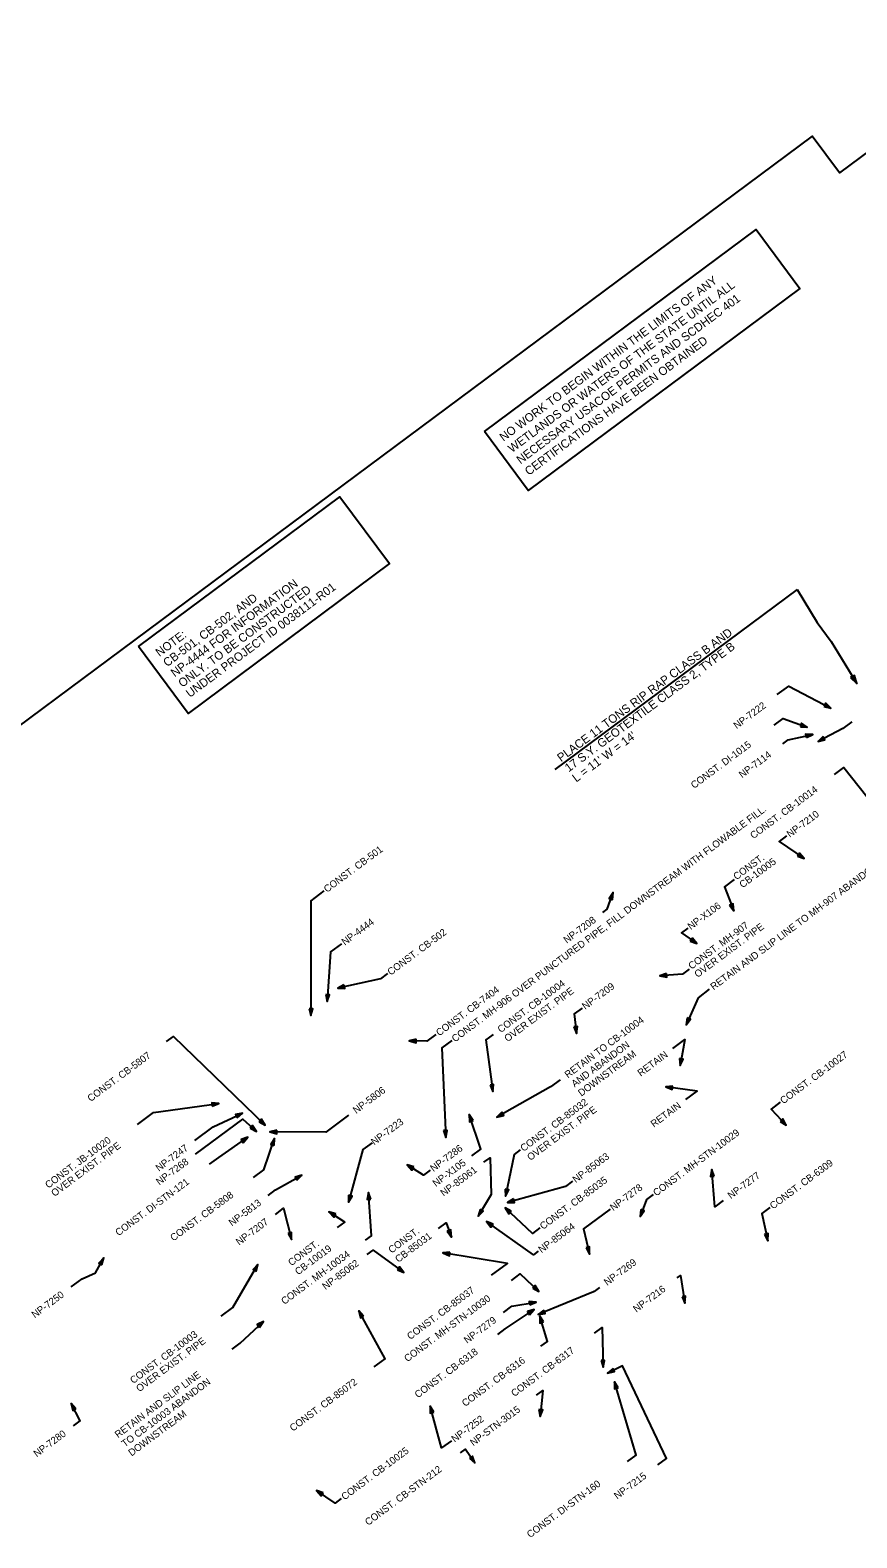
# Model space of a CAD drawing. Extents: x 1612334 to 1614149, y 1094755 to 1096548.
# Drawn here: x 1612860 to 1613444, y 1095452 to 1096518 of the extents above; entities that cross this region are included whole.
import ezdxf

# ---------------------------------------------------------------- set-up
doc = ezdxf.new("R2010")
doc.units = 0
for name, color, linetype in [('Level 11', 7, 'Continuous'), ('Level 15', 7, 'Continuous'), ('RD_HY_DumbNodes', 7, 'Continuous')]:
    doc.layers.add(name, color=color, linetype=linetype)

msp = doc.modelspace()

# ---------------------------------------------------------------- linework, layer by layer
at = {"layer": 'Level 11'}
msp.add_lwpolyline([(1613180.6, 1096234), (1613372.6, 1096376.7), (1613403.5, 1096335.1), (1613211.5, 1096192.4)], close=True, dxfattribs=at)
at = {"layer": 'Level 15'}
msp.add_lwpolyline([(1612485.6, 1095458.4), (1612588.4, 1095320.1), (1612593, 1095313.9), (1612580.2, 1095304.3), (1612634.5, 1095231.1), (1612645.5, 1095216.3), (1612653.4, 1095198.5), (1612742.5, 1095078.7), (1612868, 1094853.9), (1614076.2, 1095752), (1613959.1, 1095956.1), (1613849.9, 1096103.1), (1613853.4, 1096105.7), (1613781.7, 1096202.2), (1613794.6, 1096211.8), (1613636.5, 1096424.5), (1613567.4, 1096517.5), (1613431.6, 1096416.6), (1613412.2, 1096442.7), (1612334.4, 1095641.5)], close=True, dxfattribs=at)
msp.add_lwpolyline([(1612485.6, 1095458.4), (1612588.4, 1095320.1), (1612593, 1095313.9), (1612580.2, 1095304.3), (1612634.5, 1095231.1), (1612645.5, 1095216.3), (1612653.4, 1095198.5), (1612742.5, 1095078.7), (1612868, 1094853.9), (1614076.2, 1095752), (1613959.1, 1095956.1), (1613849.9, 1096103.1), (1613853.4, 1096105.7), (1613781.7, 1096202.2), (1613794.6, 1096211.8), (1613636.5, 1096424.5), (1613567.4, 1096517.5), (1613431.6, 1096416.6), (1613412.2, 1096442.7), (1612334.4, 1095641.5)], close=True, dxfattribs=at)
msp.add_lwpolyline([(1612485.6, 1095458.4), (1612588.4, 1095320.1), (1612593, 1095313.9), (1612580.2, 1095304.3), (1612634.5, 1095231.1), (1612645.5, 1095216.3), (1612653.4, 1095198.5), (1612742.5, 1095078.7), (1612868, 1094853.9), (1614076.2, 1095752), (1613959.1, 1095956.1), (1613849.9, 1096103.1), (1613853.4, 1096105.7), (1613781.7, 1096202.2), (1613794.6, 1096211.8), (1613636.5, 1096424.5), (1613567.4, 1096517.5), (1613431.6, 1096416.6), (1613412.2, 1096442.7), (1612334.4, 1095641.5)], close=True, dxfattribs=at)
msp.add_lwpolyline([(1612485.6, 1095458.4), (1612588.4, 1095320.1), (1612593, 1095313.9), (1612580.2, 1095304.3), (1612634.5, 1095231.1), (1612645.5, 1095216.3), (1612653.4, 1095198.5), (1612742.5, 1095078.7), (1612868, 1094853.9), (1614076.2, 1095752), (1613959.1, 1095956.1), (1613849.9, 1096103.1), (1613853.4, 1096105.7), (1613781.7, 1096202.2), (1613794.6, 1096211.8), (1613636.5, 1096424.5), (1613567.4, 1096517.5), (1613431.6, 1096416.6), (1613412.2, 1096442.7), (1612334.4, 1095641.5)], close=True, dxfattribs=at)
msp.add_lwpolyline([(1612485.6, 1095458.4), (1612588.4, 1095320.1), (1612593, 1095313.9), (1612580.2, 1095304.3), (1612634.5, 1095231.1), (1612645.5, 1095216.3), (1612653.4, 1095198.5), (1612742.5, 1095078.7), (1612868, 1094853.9), (1614076.2, 1095752), (1613959.1, 1095956.1), (1613849.9, 1096103.1), (1613853.4, 1096105.7), (1613781.7, 1096202.2), (1613794.6, 1096211.8), (1613636.5, 1096424.5), (1613567.4, 1096517.5), (1613431.6, 1096416.6), (1613412.2, 1096442.7), (1612334.4, 1095641.5)], close=True, dxfattribs=at)
msp.add_lwpolyline([(1612485.6, 1095458.4), (1612588.4, 1095320.1), (1612593, 1095313.9), (1612580.2, 1095304.3), (1612634.5, 1095231.1), (1612645.5, 1095216.3), (1612653.4, 1095198.5), (1612742.5, 1095078.7), (1612868, 1094853.9), (1614076.2, 1095752), (1613959.1, 1095956.1), (1613849.9, 1096103.1), (1613853.4, 1096105.7), (1613781.7, 1096202.2), (1613794.6, 1096211.8), (1613636.5, 1096424.5), (1613567.4, 1096517.5), (1613431.6, 1096416.6), (1613412.2, 1096442.7), (1612334.4, 1095641.5)], close=True, dxfattribs=at)
msp.add_lwpolyline([(1612485.6, 1095458.4), (1612588.4, 1095320.1), (1612593, 1095313.9), (1612580.2, 1095304.3), (1612634.5, 1095231.1), (1612645.5, 1095216.3), (1612653.4, 1095198.5), (1612742.5, 1095078.7), (1612868, 1094853.9), (1614076.2, 1095752), (1613959.1, 1095956.1), (1613849.9, 1096103.1), (1613853.4, 1096105.7), (1613781.7, 1096202.2), (1613794.6, 1096211.8), (1613636.5, 1096424.5), (1613567.4, 1096517.5), (1613431.6, 1096416.6), (1613412.2, 1096442.7), (1612334.4, 1095641.5)], close=True, dxfattribs=at)
msp.add_lwpolyline([(1612485.6, 1095458.4), (1612588.4, 1095320.1), (1612593, 1095313.9), (1612580.2, 1095304.3), (1612634.5, 1095231.1), (1612645.5, 1095216.3), (1612653.4, 1095198.5), (1612742.5, 1095078.7), (1612868, 1094853.9), (1614076.2, 1095752), (1613959.1, 1095956.1), (1613849.9, 1096103.1), (1613853.4, 1096105.7), (1613781.7, 1096202.2), (1613794.6, 1096211.8), (1613636.5, 1096424.5), (1613567.4, 1096517.5), (1613431.6, 1096416.6), (1613412.2, 1096442.7), (1612334.4, 1095641.5)], close=True, dxfattribs=at)
at = {"layer": 'RD_HY_DumbNodes'}
msp.add_line((1613401.6, 1096122.4), (1613230.5, 1095995.3), dxfattribs=at)
for points in [[(1612936.1, 1096082.1), (1613078.5, 1096187.9), (1613113.6, 1096140.7), (1612971.2, 1096034.8)], [(1613439.4, 1096060.1), (1613443.7, 1096055.9), (1613442.1, 1096061.7)], [(1613420.6, 1096039.7), (1613425.5, 1096038.6), (1613421.8, 1096042)], [(1613403.9, 1096025.4), (1613408.8, 1096025), (1613404.8, 1096027.9)], [(1613408.2, 1096017.7), (1613412.6, 1096020), (1613407.6, 1096020.2)], [(1613420, 1096018.4), (1613416.4, 1096015), (1613421.2, 1096016.1)], [(1613401.9, 1095934), (1613406.6, 1095932.4), (1613403.4, 1095936.2)], [(1613271.2, 1095903.2), (1613271.7, 1095908.2), (1613268.8, 1095904.1)], [(1613353.9, 1095899.4), (1613356.9, 1095895.4), (1613356.3, 1095900.4)], [(1613326.1, 1095874), (1613330.8, 1095872.3), (1613327.6, 1095876.1)], [(1613309.4, 1095851.1), (1613304.7, 1095849.5), (1613309.6, 1095848.6)], [(1613068.5, 1095836.2), (1613069.4, 1095831.3), (1613071.1, 1095836.1)], [(1613081.4, 1095843), (1613077, 1095840.7), (1613082, 1095840.5)], [(1613056.7, 1095826.1), (1613058, 1095821.3), (1613059.3, 1095826.1)], [(1613243.8, 1095813.4), (1613245.6, 1095808.8), (1613246.4, 1095813.7)], [(1613323.9, 1095819.8), (1613323.1, 1095814.9), (1613326.3, 1095818.8)], [(1613132.3, 1095804.7), (1613127.5, 1095803.5), (1613132.3, 1095802.1)], [(1613318.5, 1095791), (1613318.9, 1095786), (1613321.1, 1095790.6)], [(1613184.6, 1095772.3), (1613186.5, 1095767.7), (1613187.1, 1095772.6)], [(1613313.7, 1095771.6), (1613308.8, 1095771), (1613313.4, 1095769.1)], [(1612988.3, 1095757.3), (1612993, 1095759.2), (1612988, 1095759.8)], [(1613005.9, 1095749.2), (1613009.7, 1095752.4), (1613004.8, 1095751.5)], [(1613021.4, 1095746.3), (1613025.8, 1095743.9), (1613023.2, 1095748.2)], [(1613172.6, 1095747.3), (1613169.8, 1095751.4), (1613170.2, 1095746.4)], [(1613193, 1095753.1), (1613189.4, 1095749.6), (1613194.3, 1095750.8)], [(1613389.6, 1095746.6), (1613393.8, 1095743.9), (1613391.5, 1095748.4)], [(1613015, 1095741.8), (1613019.5, 1095739.5), (1613016.7, 1095743.7)], [(1613033.9, 1095740.5), (1613029.1, 1095739.2), (1613033.9, 1095737.9)], [(1613151.8, 1095740.1), (1613153.3, 1095735.3), (1613154.3, 1095740.2)], [(1613010.2, 1095731.5), (1613013.4, 1095735.4), (1613008.7, 1095733.7)], [(1613032, 1095729.5), (1613032.4, 1095734.5), (1613029.6, 1095730.3)], [(1613130.8, 1095714.4), (1613126, 1095715.8), (1613129.4, 1095712.2)], [(1613048, 1095705.1), (1613051.6, 1095708.5), (1613046.8, 1095707.3)], [(1613343.1, 1095707.9), (1613341.4, 1095712.6), (1613340.5, 1095707.7)], [(1613084.7, 1095694.5), (1613084.7, 1095689.5), (1613087.2, 1095693.8)], [(1613100.3, 1095691.6), (1613098.7, 1095696.3), (1613097.7, 1095691.4)], [(1613195.3, 1095698.8), (1613195.6, 1095693.8), (1613197.9, 1095698.2)], [(1613177.6, 1095684.4), (1613176.3, 1095679.6), (1613179.8, 1095683.1)], [(1613199.6, 1095683.2), (1613195.2, 1095685.5), (1613197.8, 1095681.2)], [(1613201.3, 1095691.8), (1613197, 1095689.2), (1613202, 1095689.3)], [(1613291.1, 1095684.4), (1613290.6, 1095679.5), (1613293.5, 1095683.5)], [(1613075.6, 1095681.2), (1613070.8, 1095682.7), (1613074.2, 1095679)], [(1613186.7, 1095674.1), (1613182, 1095675.8), (1613185.2, 1095671.9)], [(1613041.9, 1095667.4), (1613044.3, 1095663.1), (1613044.4, 1095668.1)], [(1613154.4, 1095669), (1613157.3, 1095664.9), (1613156.8, 1095669.9)], [(1613378.6, 1095666.8), (1613380.9, 1095662.3), (1613381.2, 1095667.3)], [(1613156.3, 1095654.3), (1613151.3, 1095653.8), (1613155.9, 1095651.7)], [(1613252.5, 1095657.3), (1613254.9, 1095652.9), (1613255, 1095657.9)], [(1612910.3, 1095645.3), (1612911.6, 1095650.1), (1612908.1, 1095646.5)], [(1613019.3, 1095640.6), (1613020.6, 1095645.4), (1613017.1, 1095641.9)], [(1613119.1, 1095641.7), (1613123.8, 1095639.9), (1613120.6, 1095643.8)], [(1613214.8, 1095628.7), (1613219.2, 1095626.4), (1613216.5, 1095630.6)], [(1613320.3, 1095622.7), (1613322.3, 1095618.1), (1613322.8, 1095623.1)], [(1613095.3, 1095609.1), (1613091.8, 1095612.7), (1613093, 1095607.9)], [(1613212.5, 1095610), (1613215.8, 1095613.8), (1613211, 1095612.2)], [(1613212.8, 1095616.9), (1613217.3, 1095619), (1613212.3, 1095619.4)], [(1613222.7, 1095613.3), (1613218.7, 1095610.2), (1613223.6, 1095610.9)], [(1613222.3, 1095604.9), (1613219.7, 1095609.1), (1613219.9, 1095604.1)], [(1613021.7, 1095601.1), (1613024.4, 1095605.3), (1613020, 1095603)], [(1613263.1, 1095577.7), (1613264.5, 1095572.9), (1613265.6, 1095577.8)], [(1613271.5, 1095572.1), (1613267.7, 1095568.8), (1613272.6, 1095569.8)], [(1613275.1, 1095558.4), (1613272.5, 1095562.7), (1613272.6, 1095557.7)], [(1612892, 1095543.6), (1612888.6, 1095547.3), (1612889.7, 1095542.4)], [(1613144.9, 1095541.1), (1613142.4, 1095545.4), (1613142.4, 1095540.4)], [(1613219.2, 1095543.1), (1613220, 1095538.1), (1613221.8, 1095542.8)], [(1613170.2, 1095508.6), (1613173.9, 1095505.3), (1613172.3, 1095510)], [(1613066.7, 1095484.2), (1613062, 1095485.8), (1613065.3, 1095482)]]:
    msp.add_lwpolyline(points, close=True, dxfattribs=at)
for points in [[(1613401.6, 1096122.4), (1613415.8, 1096099), (1613425.7, 1096085.6), (1613443.7, 1096055.9)], [(1613387.6, 1096048.1), (1613395.7, 1096054.1), (1613425.5, 1096038.6)], [(1613385.4, 1096026.6), (1613391.7, 1096031.3), (1613408.8, 1096025)], [(1613440.3, 1096028.9), (1613434, 1096024.2), (1613416.4, 1096015)], [(1613391.5, 1096013.4), (1613395.3, 1096016.2), (1613412.6, 1096020)], [(1613428.1, 1095991.6), (1613434.7, 1095996.5), (1613456.4, 1095969.4)], [(1613394.2, 1095948.3), (1613389, 1095944.4), (1613406.6, 1095932.4)], [(1613067.1, 1095909.4), (1613057.9, 1095902.5), (1613058, 1095821.3)], [(1613264.4, 1095894.2), (1613267.4, 1095896.5), (1613271.7, 1095908.2)], [(1613357.1, 1095917.5), (1613350.3, 1095912.4), (1613356.9, 1095895.4)], [(1613324.3, 1095883.1), (1613319.9, 1095879.8), (1613330.8, 1095872.3)], [(1613079.7, 1095872.1), (1613071.9, 1095866.3), (1613069.4, 1095831.3)], [(1613325.3, 1095854.2), (1613320.6, 1095850.7), (1613304.7, 1095849.5)], [(1613112.1, 1095851), (1613107.2, 1095847.3), (1613077, 1095840.7)], [(1613339.5, 1095839.9), (1613331.6, 1095834), (1613323.1, 1095814.9)], [(1613249.7, 1095826.7), (1613244.1, 1095822.6), (1613245.6, 1095808.8)], [(1612955.9, 1095803), (1612960.8, 1095806.6), (1613025.8, 1095743.9)], [(1613146.4, 1095808), (1613140, 1095803.3), (1613127.5, 1095803.5)], [(1613157.5, 1095803.7), (1613150.6, 1095798.6), (1613153.3, 1095735.3)], [(1613186.7, 1095807.9), (1613181.7, 1095804.2), (1613186.5, 1095767.7)], [(1613313.7, 1095798), (1613322.3, 1095804.4), (1613318.9, 1095786)], [(1613234.1, 1095775.9), (1613227.3, 1095770.9), (1613189.4, 1095749.6)], [(1613322.9, 1095762), (1613331, 1095768), (1613308.8, 1095771)], [(1612935.4, 1095744.4), (1612946.8, 1095752.9), (1612993, 1095759.2)], [(1613389.6, 1095760.1), (1613383.2, 1095755.3), (1613393.8, 1095743.9)], [(1612976.1, 1095733.1), (1612989, 1095742.7), (1613009.7, 1095752.4)], [(1612976.4, 1095723.4), (1613009.8, 1095748.2), (1613019.5, 1095739.5)], [(1613084.5, 1095750.9), (1613068.6, 1095739), (1613029.1, 1095739.2)], [(1613171.8, 1095722.3), (1613178.2, 1095727), (1613169.8, 1095751.4)], [(1612986.4, 1095716.3), (1612992.9, 1095721.2), (1613013.4, 1095735.4)], [(1613017.5, 1095706.9), (1613024.8, 1095712.4), (1613032.4, 1095734.5)], [(1613101.3, 1095731.5), (1613094.8, 1095726.7), (1613084.7, 1095689.5)], [(1613206, 1095726.4), (1613201.7, 1095723.2), (1613195.6, 1095693.8)], [(1613142.3, 1095712.2), (1613137.5, 1095708.7), (1613126, 1095715.8)], [(1613180.3, 1095717.7), (1613184.6, 1095720.9), (1613185.3, 1095695), (1613176.3, 1095679.6)], [(1613027.7, 1095694.3), (1613032.9, 1095698.2), (1613051.6, 1095708.5)], [(1613349.3, 1095690.6), (1613343.5, 1095686.3), (1613341.4, 1095712.6)], [(1613096.7, 1095662.7), (1613100.9, 1095665.8), (1613098.7, 1095696.3)], [(1613242.9, 1095704.3), (1613237.9, 1095700.6), (1613197, 1095689.2)], [(1613299.8, 1095694.9), (1613295.2, 1095691.5), (1613290.6, 1095679.5)], [(1613032.9, 1095680.9), (1613038.6, 1095685.2), (1613044.3, 1095663.1)], [(1613219.8, 1095671.3), (1613214.7, 1095667.5), (1613195.2, 1095685.5)], [(1613269.4, 1095684.5), (1613250.7, 1095670.6), (1613254.9, 1095652.9)], [(1613382.3, 1095685.7), (1613376.7, 1095681.5), (1613380.9, 1095662.3)], [(1613076.9, 1095671.6), (1613082.1, 1095675.5), (1613070.8, 1095682.7)], [(1613148.3, 1095671), (1613153.5, 1095674.9), (1613157.3, 1095664.9)], [(1613218.7, 1095654.9), (1613215.2, 1095652.3), (1613182, 1095675.8)], [(1613097.8, 1095652.5), (1613102.1, 1095655.6), (1613123.8, 1095639.9)], [(1613185.6, 1095637.9), (1613196.9, 1095646.3), (1613151.3, 1095653.8)], [(1612888.7, 1095629.7), (1612896.4, 1095635.4), (1612905.7, 1095639.7), (1612911.6, 1095650.1)], [(1612994.6, 1095609), (1613002.9, 1095615.1), (1613020.6, 1095645.4)], [(1613199.8, 1095634.3), (1613205.9, 1095638.8), (1613219.2, 1095626.4)], [(1613316.9, 1095636), (1613319.2, 1095637.7), (1613322.3, 1095618.1)], [(1613261.9, 1095629.3), (1613258.1, 1095626.4), (1613257.7, 1095626.1), (1613218.7, 1095610.2)], [(1613102.7, 1095573.1), (1613110.6, 1095578.9), (1613091.8, 1095612.7)], [(1613190.2, 1095596.1), (1613195.4, 1095600), (1613215.8, 1095613.8)], [(1613194, 1095611.5), (1613200, 1095616), (1613217.3, 1095619)], [(1613220.6, 1095587.8), (1613225.2, 1095591.2), (1613219.7, 1095609.1)], [(1613002.4, 1095585.7), (1613008, 1095589.9), (1613024.4, 1095605.3)], [(1613258.4, 1095597), (1613263.8, 1095600.9), (1613264.5, 1095572.9)], [(1613303.2, 1095503.9), (1613309.3, 1095508.4), (1613278.2, 1095574), (1613267.7, 1095568.8)], [(1613217.5, 1095553.3), (1613221.8, 1095556.5), (1613220, 1095538.1)], [(1613281.8, 1095506.4), (1613287.8, 1095510.9), (1613272.5, 1095562.7)], [(1612890.2, 1095531.5), (1612894.9, 1095535.1), (1612888.6, 1095547.3)], [(1613157.3, 1095521), (1613150.4, 1095515.9), (1613142.4, 1095545.4)], [(1613163.8, 1095512.5), (1613167.3, 1095515.1), (1613173.9, 1095505.3)], [(1613079.5, 1095480.3), (1613075.1, 1095477), (1613062, 1095485.8)]]:
    msp.add_lwpolyline(points, dxfattribs=at)

# ---------------------------------------------------------------- texts
at = {"layer": 'Level 11'}
for s, p in [('NO WORK TO BEGIN WITHIN THE LIMITS OF ANY', (1613194.1, 1096226.7)), ('WETLANDS OR WATERS OF THE STATE UNTIL ALL', (1613200.1, 1096218.7)), ('NECESSARY USACOE PERMITS AND SCDHEC 401', (1613206.1, 1096210.7)), ('CERTIFICATIONS HAVE BEEN OBTAINED', (1613212, 1096202.6))]:
    msp.add_text(s, height=6, rotation=36.6255, dxfattribs=at).set_placement(p)
at = {"layer": 'RD_HY_DumbNodes'}
for s, height, rotation, p in [('NP-4444 FOR INFORMATION', 6, 36.624, (1612961.8, 1096060.2)), ('ONLY. TO BE CONSTRUCTED', 6, 36.624, (1612967.1, 1096052.9)), ('UNDER PROJECT ID 0038111-R01', 6, 36.624, (1612972.5, 1096045.7)), ('CB-501, CB-502, AND ', 6, 36.624, (1612956.4, 1096067.4)), ('NOTE:', 6, 36.624, (1612951, 1096074.6)), ('PLACE 11 TONS RIP RAP CLASS B AND', 6, 36.6256, (1613234.8, 1096000.3)), ('17 S.Y. GEOTEXTILE CLASS 2, TYPE B', 6, 36.6256, (1613240.2, 1095993.1)), ('NP-7222', 5, 36.624, (1613358.9, 1096023.6)), ("L = 11' W = 14'", 6, 36.6256, (1613245.5, 1095985.9)), ('CONST. DI-1015', 5, 36.624, (1613328.8, 1095981.4)), ('NP-7114', 5, 36.624, (1613362.7, 1095988.9)), ('CONST. CB-10014', 5, 36.624, (1613370.7, 1095945.9)), ('CONST. MH-906 OVER PUNCTURED PIPE, FILL DOWNSTREAM WITH FLOWABLE FILL.', 5, 36.624, (1613159.8, 1095802.3)), ('NP-7210', 5, 36.624, (1613396.5, 1095946.9)), ('RETAIN AND SLIP LINE TO MH-907 ABANDON DOWNSTREAM', 5, 36.624, (1613342.6, 1095839.1)), ('CONST. CB-501', 5, 36.624, (1613069.4, 1095908)), ('CONST.', 5, 36.624, (1613358.8, 1095916.9)), ('CB-10005', 5, 36.624, (1613363.1, 1095911.2)), ('NP-X106', 5, 36.624, (1613326.5, 1095881.7)), ('NP-4444', 5, 36.624, (1613082, 1095870.7)), ('NP-7208', 5, 36.624, (1613238.8, 1095872.1)), ('CONST. MH-907', 5, 36.624, (1613327, 1095853.7)), ('OVER EXIST. PIPE', 5, 36.624, (1613331.3, 1095847.9)), ('CONST. CB-502', 5, 36.624, (1613114.4, 1095849.5)), ('CONST. CB-10004', 5, 36.624, (1613192.2, 1095808.9)), ('NP-7209', 5, 36.624, (1613251.9, 1095825.3)), ('CONST. CB-7404', 5, 36.624, (1613148.7, 1095806.6)), ('OVER EXIST. PIPE', 5, 36.624, (1613197, 1095802.5)), ('RETAIN TO CB-10004', 5, 36.624, (1613239.6, 1095776.9)), ('AND ABANDON', 5, 36.624, (1613244.4, 1095770.5)), ('CONST. CB-5807', 5, 36.624, (1612902.4, 1095760.2)), ('DOWNSTREAM', 5, 36.624, (1613249.1, 1095764)), ('RETAIN', 5, 36.624, (1613291.1, 1095778.1)), ('CONST. CB-10027', 5, 36.624, (1613391.9, 1095758.6)), ('NP-5806', 5, 36.624, (1613090, 1095751.8)), ('CONST. CB-85032', 5, 36.624, (1613208.3, 1095725)), ('RETAIN', 5, 36.624, (1613300.4, 1095742.1)), ('NP-7223', 5, 36.624, (1613102.8, 1095729.5)), ('OVER EXIST. PIPE', 5, 36.624, (1613213.1, 1095718.6)), ('CONST. MH-STN-10029', 5, 36.624, (1613302.1, 1095693.5)), ('CONST. JB-10020', 5, 36.624, (1612872.5, 1095699)), ('OVER EXIST. PIPE', 5, 36.624, (1612876.8, 1095693.2)), ('NP-7247', 5, 36.624, (1612950.6, 1095711)), ('NP-7286', 5, 36.624, (1613144.6, 1095710.8)), ('NP-7268', 5, 36.624, (1612950.9, 1095701.3)), ('NP-X105', 5, 36.624, (1613146.3, 1095700.2)), ('NP-85063', 5, 36.624, (1613245.2, 1095702.9)), ('CONST. CB-6309', 5, 36.624, (1613384.6, 1095684.3)), ('CONST. DI-STN-121', 5, 36.624, (1612922.1, 1095665.4)), ('NP-85061', 5, 36.624, (1613151.8, 1095693.4)), ('CONST. CB-85035', 5, 36.624, (1613222.1, 1095669.9)), ('NP-7277', 5, 36.624, (1613354.8, 1095691.6)), ('CONST. CB-5808', 5, 36.624, (1612960.9, 1095661.7)), ('NP-7278', 5, 36.624, (1613271.7, 1095683.1)), ('NP-5813', 5, 36.624, (1613002.2, 1095672.3)), ('NP-7207', 5, 36.624, (1613007.3, 1095658.8)), ('NP-85064', 5, 36.624, (1613221, 1095653.4)), ('CONST.', 5, 36.624, (1613115, 1095653.1)), ('CB-85031', 5, 36.624, (1613119.8, 1095646.6)), ('CONST. MH-10034', 5, 36.624, (1613039.3, 1095616.9)), ('CONST.', 5, 36.624, (1613044.2, 1095644.2)), ('CB-10019', 5, 36.624, (1613049, 1095637.8)), ('NP-85062', 5, 36.624, (1613068.3, 1095627.4)), ('NP-7269', 5, 36.624, (1613267.4, 1095630.3)), ('NP-7216', 5, 36.624, (1613288, 1095611.4)), ('NP-7250', 5, 36.624, (1612862.9, 1095607.4)), ('CONST. MH-STN-10030', 5, 36.624, (1613126.2, 1095576.4)), ('CONST. CB-85037', 5, 36.624, (1613128.2, 1095592.1)), ('CONST. CB-10003', 5, 36.624, (1612932.5, 1095561)), ('NP-7279', 5, 36.624, (1613168.4, 1095589.4)), ('OVER EXIST. PIPE', 5, 36.624, (1612936.8, 1095555.2)), ('CONST. CB-6318', 5, 36.624, (1613133.6, 1095550.9)), ('CONST. CB-6316', 5, 36.624, (1613167, 1095544.8)), ('CONST. CB-6317', 5, 36.624, (1613201.8, 1095551.8)), ('RETAIN AND SLIP LINE', 5, 36.624, (1612921.7, 1095522.7)), ('TO CB-10003 ABANDON', 5, 36.624, (1612926.5, 1095516.2)), ('CONST. CB-85072', 5, 36.624, (1613045.3, 1095527.3)), ('NP-STN-3015', 5, 36.624, (1613172.8, 1095517)), ('DOWNSTREAM', 5, 36.624, (1612931.3, 1095509.8)), ('NP-7252', 5, 36.624, (1613159.6, 1095519.6)), ('NP-7280', 5, 36.624, (1612864.3, 1095509.2)), ('CONST. CB-10025', 5, 36.624, (1613081.8, 1095478.8)), ('CONST. CB-STN-212', 5, 36.624, (1613098.5, 1095460.8)), ('CONST. DI-STN-160', 5, 36.624, (1613212.9, 1095452.1)), ('NP-7215', 5, 36.624, (1613274.5, 1095479.4))]:
    msp.add_text(s, height=height, rotation=rotation, dxfattribs=at).set_placement(p)

doc.saveas('drawing.dxf')
